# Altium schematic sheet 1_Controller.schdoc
size 431 x 309 mm
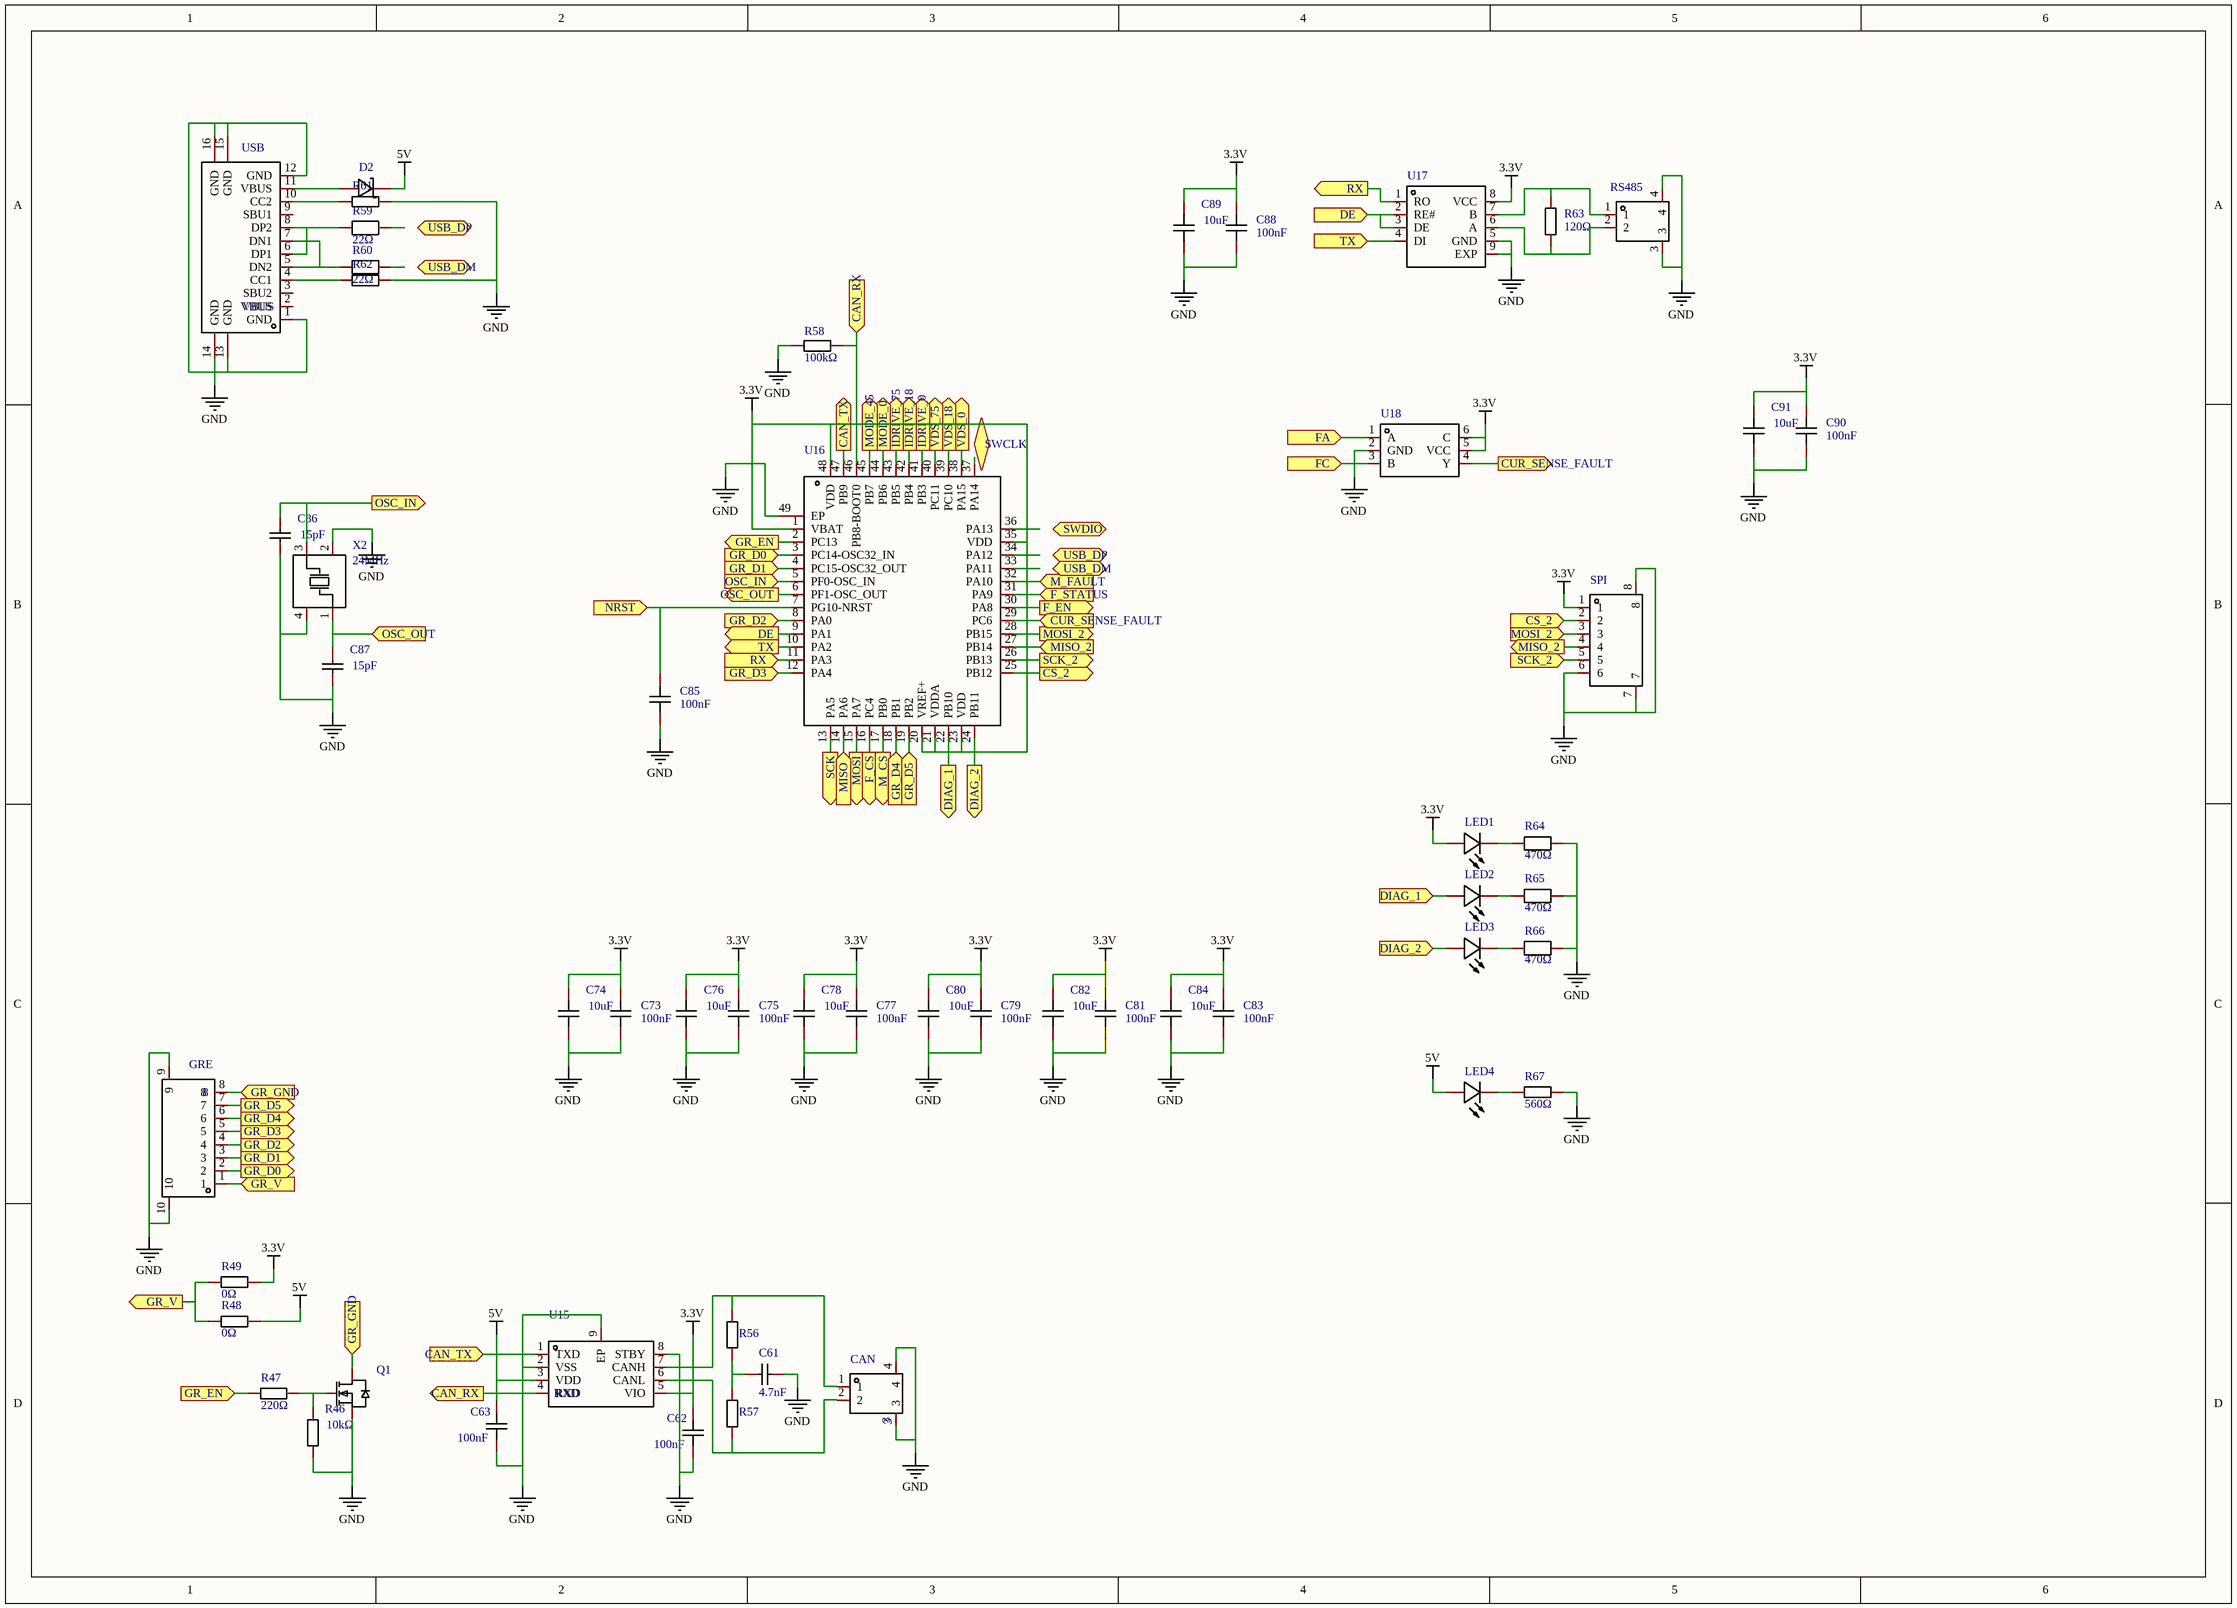
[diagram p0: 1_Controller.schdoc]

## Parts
C61  value 4.7nF  [C0402]  (hidden comment: 0402B472K500CT)
C62  value 100nF  [C0402]  (hidden comment: CC0402KRX7R7BB104)
C63  value 100nF  [C0402]  (hidden comment: CC0402KRX7R7BB104)
C73  value 100nF  [C0402]  (hidden comment: CC0402KRX7R7BB104)
C74  value 10uF  [C0402]  (hidden comment: CL05A106MP5NUNC)
C75  value 100nF  [C0402]  (hidden comment: CC0402KRX7R7BB104)
C76  value 10uF  [C0402]  (hidden comment: CL05A106MP5NUNC)
C77  value 100nF  [C0402]  (hidden comment: CC0402KRX7R7BB104)
C78  value 10uF  [C0402]  (hidden comment: CL05A106MP5NUNC)
C79  value 100nF  [C0402]  (hidden comment: CC0402KRX7R7BB104)
C80  value 10uF  [C0402]  (hidden comment: CL05A106MP5NUNC)
C81  value 100nF  [C0402]  (hidden comment: CC0402KRX7R7BB104)
C82  value 10uF  [C0402]  (hidden comment: CL05A106MP5NUNC)
C83  value 100nF  [C0402]  (hidden comment: CC0402KRX7R7BB104)
C84  value 10uF  [C0402]  (hidden comment: CL05A106MP5NUNC)
C85  value 100nF  [C0402]  (hidden comment: CC0402KRX7R7BB104)
C86  value 15pF  [C0402]  (hidden comment: 0402CG150J500NT)
C87  value 15pF  [C0402]  (hidden comment: 0402CG150J500NT)
C88  value 100nF  [C0402]  (hidden comment: CC0402KRX7R7BB104)
C89  value 10uF  [C0402]  (hidden comment: CL05A106MP5NUNC)
C90  value 100nF  [C0402]  (hidden comment: CC0402KRX7R7BB104)
C91  value 10uF  [C0402]  (hidden comment: CL05A106MP5NUNC)
CAN  NUMBER: 3  [CONN-SMD_A1002WR-S-2P]  (hidden comment: A1002WR-S-2P)
D2  DSK16  [SOD-123_L2.8-W1.8-LS3.7-RD]  (value not drawn)
GRE  NAME: 8  [CONN-SMD_A1002WR-S-8P]  (hidden comment: A1002WR-S-8P)
LED1  MHT136UBCT  [LED0402-RD_BLUE]  (value not drawn)
LED2  MHT136UBCT  [LED0402-RD_BLUE]  (value not drawn)
LED3  MHT136UBCT  [LED0402-RD_BLUE]  (value not drawn)
LED4  MHT136CSCT  [LED0402-RD_ORANGE]  (value not drawn)
Q1  AP2302B  [SOT-23_L2.9-W1.3-P1.90-LS2.4-BR]  (value not drawn)
R46  value 10kΩ  [R0402]  (hidden comment: AC0402FR-0710KL)
R47  value 220Ω  [R0402]  (hidden comment: 0402WGF2200TCE)
R48  value 0Ω  [R0402]  (hidden comment: RC0402FR-070RL)
R49  value 0Ω  [R0402]  (hidden comment: RC0402FR-070RL)
R56  0402WGF604JTCE  [R0402]  (value not drawn)
R57  0402WGF604JTCE  [R0402]  (value not drawn)
R58  value 100kΩ  [R0402]  (hidden comment: PTFR0402B100KN9)
R59  value 22Ω  [R0402]  (hidden comment: AC0402FR-0722RL)
R60  value 22Ω  [R0402]  (hidden comment: AC0402FR-0722RL)
R61  0402WGF5101TCE  [R0402]  (value not drawn)
R62  0402WGF5101TCE  [R0402]  (value not drawn)
R63  value 120Ω  [R0402]  (hidden comment: RC0402FR-07120RL)
R64  value 470Ω  [R0402]  (hidden comment: AC0402FR-07470RL)
R65  value 470Ω  [R0402]  (hidden comment: AC0402FR-07470RL)
R66  value 470Ω  [R0402]  (hidden comment: AC0402FR-07470RL)
R67  value 560Ω  [R0402]  (hidden comment: 0402WGJ0561TCE)
RS485  A1002WR-S-2P  [CONN-SMD_A1002WR-S-2P]  (value not drawn)
SPI  A1002WR-S-6P  [CONN-SMD_A1002WR-S-6P]  (value not drawn)
U15  NAME: RXD  [TDFN-8_L3.0-W2.0-P0.50-TL-EP]  (hidden comment: MCP2542FDT-H/MNY)
U16  STM32G431CBU6  [UFQFPN-48_L7.0-W7.0-P0.50-BL-EP]  (value not drawn)
U17  MAX14841EATA+T  [TDFN-8_L3.0-W3.0-P0.65-BL-EP]  (value not drawn)
U18  SN74LVC1G10DSFR  [X2SON-6_L1.0-W1.0-P0.35-TL]  (value not drawn)
USB  NAME: VBUS  [USB-SMD_GT-USB-7010B]  (hidden comment: GT-USB-7010B)
X2  value 24MHz  [CRYSTAL-SMD_4P-L3.2-W2.5-BL]  (hidden comment: X322524MOB4SI)

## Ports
CAN_RX (in), CAN_RX (out), CAN_TX (in), CAN_TX (out), CS_2 (in), CS_2 (out), CUR_SENSE_FAULT (in), CUR_SENSE_FAULT (out), DE (in), DE (out), DIAG_1 (in), DIAG_1 (out), DIAG_2 (in), DIAG_2 (out), F_CS (out), F_EN (out), F_STATUS (in), FA (in), FC (in), GR_D0 (in), GR_D0 (out), GR_D1 (in), GR_D1 (out), GR_D2 (in), GR_D2 (out), GR_D3 (in), GR_D3 (out), GR_D4 (in), GR_D4 (out), GR_D5 (in), GR_D5 (out), GR_EN (in), GR_EN (out), GR_GND (in), GR_V (in), GR_V (out), IDRIVE_0 (out), IDRIVE_18 (out), IDRIVE_75 (out), M_CS (out), M_FAULT (in), MISO (in), MISO_2 (in), MISO_2 (out), MODE_0 (out), MODE_45 (out), MOSI (out), MOSI_2 (in), MOSI_2 (out), NRST (in), OSC_IN (in), OSC_IN (out), OSC_OUT (in), OSC_OUT (out), RX (in), RX (out), SCK (out), SCK_2 (in), SCK_2 (out), SWCLK (bidir), SWDIO (bidir), TX (in), TX (out), USB_DM (bidir), USB_DP (bidir), VDS_0 (out), VDS_18 (out), VDS_75 (out)

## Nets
3.3V: C62.1 C73.1 C74.2 C75.1 C76.2 C77.1 C78.2 C79.1 C80.2 C81.1 C82.2 C83.1 C84.2 C88.1 C89.2 C90.1 C91.2 LED1.2(A) R49.2 SPI.1 U15.5(VIO) U16.1(VBAT) U16.20(VREF+) U16.21(VDDA) U16.23(VDD) U16.35(VDD) U16.48(VDD) U17.8(VCC) U18.5(VCC) U18.6(C)
5V: C63.1 D2.1(K) LED4.2(A) R48.2 U15.3(VDD)
GND: C61.2 C62.2 C63.2 C73.2 C74.1 C75.2 C76.1 C77.2 C78.1 C79.2 C80.1 C81.2 C82.1 C83.2 C84.1 C85.2 C86.1 C87.1 C88.2 C89.1 C90.2 C91.1 CAN.3 CAN.4 GRE.9 GRE.10 Q1.2(S) R46.1 R58.2 R61.2 R62.2 R64.2 R65.2 R66.2 R67.2 RS485.3 RS485.4 SPI.6 SPI.7 SPI.8 U15.2(VSS) U15.8(STBY) U15.9(EP) U16.49(EP) U17.5(GND) U17.9(EXP) U18.2(GND) USB.1(GND) USB.12(GND) USB.13(GND) USB.14(GND) USB.15(GND) USB.16(GND) X2.2(GND) X2.4(GND)
CAN_RX: R58.1 U15.4(RXD) U16.46(PB8-BOOT0) ; port CAN_RX
CAN_TX: U15.1(TXD) U16.47(PB9) ; port CAN_TX
CS_2: SPI.2 U16.25(PB12) ; port CS_2
CUR_SENSE_FAULT: U16.29(PC6) U18.4(Y) ; port CUR_SENSE_FAULT
DE: U16.9(PA1) U17.2(RE#) U17.3(DE) ; port DE
DIAG_1: LED2.2(A) U16.22(PB10) ; port DIAG_1
DIAG_2: LED3.2(A) U16.24(PB11) ; port DIAG_2
F_CS: U16.16(PC4) ; port F_CS
F_EN: U16.30(PA8) ; port F_EN
F_STATUS: U16.31(PA9) ; port F_STATUS
FA: U18.1(A) ; port FA
FC: U18.3(B) ; port FC
GR_D0: GRE.2 U16.3(PC14-OSC32_IN) ; port GR_D0
GR_D1: GRE.3 U16.4(PC15-OSC32_OUT) ; port GR_D1
GR_D2: GRE.4 U16.8(PA0) ; port GR_D2
GR_D3: GRE.5 U16.12(PA4) ; port GR_D3
GR_D4: GRE.6 U16.18(PB1) ; port GR_D4
GR_D5: GRE.7 U16.19(PB2) ; port GR_D5
GR_EN: R47.1 U16.2(PC13) ; port GR_EN
GR_GND: GRE.8 Q1.3(D) ; port GR_GND
GR_V: GRE.1 R48.1 R49.1 ; port GR_V
IDRIVE_0: U16.41(PB3) ; port IDRIVE_0
IDRIVE_18: U16.42(PB4) ; port IDRIVE_18
IDRIVE_75: U16.43(PB5) ; port IDRIVE_75
M_CS: U16.17(PB0) ; port M_CS
M_FAULT: U16.32(PA10) ; port M_FAULT
MISO: U16.14(PA6) ; port MISO
MISO_2: SPI.4 U16.27(PB14) ; port MISO_2
MODE_0: U16.44(PB6) ; port MODE_0
MODE_45: U16.45(PB7) ; port MODE_45
MOSI: U16.15(PA7) ; port MOSI
MOSI_2: SPI.3 U16.28(PB15) ; port MOSI_2
NRST: C85.1 U16.7(PG10-NRST) ; port NRST
OSC_IN: C86.2 U16.5(PF0-OSC_IN) X2.3(OSC2) ; port OSC_IN
OSC_OUT: C87.2 U16.6(PF1-OSC_OUT) X2.1(OSC1) ; port OSC_OUT
RX: U16.11(PA3) U17.1(RO) ; port RX
SCK: U16.13(PA5) ; port SCK
SCK_2: SPI.5 U16.26(PB13) ; port SCK_2
TX: U16.10(PA2) U17.4(DI) ; port TX
VDS_0: U16.38(PA15) ; port VDS_0
VDS_18: U16.39(PC10) ; port VDS_18
VDS_75: U16.40(PC11) ; port VDS_75
NetC61_1: C61.1 R56.2 R57.1
NetCAN_1: CAN.1 R56.1 U15.7(CANH)
NetCAN_2: CAN.2 R57.2 U15.6(CANL)
NetD2_2: D2.2(A) USB.11(VBUS)
NetLED1_1: LED1.1(K) R64.1
NetLED2_1: LED2.1(K) R65.1
NetLED3_1: LED3.1(K) R66.1
NetLED4_1: LED4.1(K) R67.1
NetQ1_1: Q1.1(G) R46.2 R47.2
NetR59_1: R59.1 USB.6(DP1) USB.8(DP2)
NetR60_1: R60.1 USB.5(DN2) USB.7(DN1)
NetR61_1: R61.1 USB.10(CC2)
NetR62_1: R62.1 USB.4(CC1)
NetR63_1: R63.1 RS485.2 U17.6(A)
NetR63_2: R63.2 RS485.1 U17.7(B)

Not connected (* = marked no-connect by the designer): R59 2; R60 2; U16 33(PA11) 34(PA12) 36(PA13) 37(PA14); USB 2(VBUS) 3(SBU2) 9(SBU1)

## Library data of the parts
C61 = 0402B472K500CT: Capacitance:4.7nF Tolerance:±10% Tolerance:±10% Voltage Rated:50V Temperature Coefficient:X7R; Manufacturer: 华新科(Walsin); Add into BOM: yes; Tolerance: ±10%; Voltage Rated: 50V; Temperature Coefficient: X7R
C62 C63 C73 C75 C77 C79 C81 C83 C85 C88 C90 = CC0402KRX7R7BB104: Capacitance:100nF Tolerance:±10% Tolerance:±10% Voltage Rated:16V Temperature Coefficient:X7R; Manufacturer: YAGEO(国巨); Add into BOM: yes; Tolerance: ±10%; Voltage Rated: 16V; Temperature Coefficient: X7R
C74 C76 C78 C80 C82 C84 C89 C91 = CL05A106MP5NUNC: Capacitance:10uF Tolerance:±20% Tolerance:±20% Voltage Rated:10V Temperature Coefficient:X5R; Manufacturer: SAMSUNG(三星); Symbol: CL05A106MP5NUNC_C315248; Add into BOM: yes; Tolerance: ±20%; Voltage Rated: 10V; Temperature Coefficient: X5R
C86 C87 = 0402CG150J500NT: Capacitance:15pF Tolerance:±5% Tolerance:±5% Voltage Rated:50V Temperature Coefficient:C0G; Manufacturer: FH(风华); Add into BOM: yes; Tolerance: ±5%; Voltage Rated: 50V; Temperature Coefficient: C0G
CAN RS485 = A1002WR-S-2P: Reference Series:SH Pitch:1mm Pins Structure:1x2P Number of Rows:1 Number of PINs Per Row:2 Row Spacing:- Mounting Style:- Contact Material:磷青铜; Manufacturer: CJT(长江连接器); Add into BOM: yes; Reference Series: SH; Pitch: 1mm; Pins Structure: 1x2P; Number of PINs Per Row: 2
D2 = DSK16: Reverse Voltage (Vr):60V Average Rectified Current (Io):1A Forward Voltage (Vf@If):700mV@1A; Manufacturer: MDD; Add into BOM: yes; Reverse Voltage (Vr): 60V; Average Rectified Current (Io): 1A
GRE = A1002WR-S-8P: Reference Series:SH Pitch:1mm Pins Structure:1x8P Number of Rows:1 Number of PINs Per Row:8 Row Spacing:- Mounting Style:- Contact Material:磷青铜; Manufacturer: CJT(长江连接器); Add into BOM: yes; Reference Series: SH; Pitch: 1mm; Pins Structure: 1x8P
LED1-LED3 = MHT136UBCT: Emitted Color:蓝灯 Diode Configuration:- Lens Color:无色透明 Dominant Wavelength:460nm~475nm Dominant Wavelength:460nm~475nm Peak Wavelength:468nm Color Temperature:- Color Temperature:- Luminous Flux (@25):- Forward Current:5mA Forward Voltage (VF):3V Luminou; Manufacturer: MEIHUA(美华科技); Add into BOM: yes; Emitted Color: 蓝灯; Lens Color: 无色透明; Peak Wavelength: 468nm; Forward Current: 5mA; Forward Voltage (VF): 3V; Luminous Intensity: 72mcd; Power Dissipation: 95mW; Viewing Angle: 120°
LED4 = MHT136CSCT: Emitted Color:橙灯 Diode Configuration:- Lens Color:无色透明 Dominant Wavelength:600.5nm~612.5nm Dominant Wavelength:600.5nm~612.5nm Peak Wavelength:611nm Color Temperature:- Color Temperature:- Luminous Flux (@25):- Forward Current:5mA Forward Voltage (VF):2.; Manufacturer: MEIHUA(美华科技); Add into BOM: yes; Emitted Color: 橙灯; Lens Color: 无色透明; Peak Wavelength: 611nm; Forward Current: 5mA; Forward Voltage (VF): 2.2V; Luminous Intensity: 72mcd; Power Dissipation: 60mW; Viewing Angle: 120°
Q1 = AP2302B: Type:N沟道 Drain Source Voltage (Vdss):20V Continuous Drain Current (Id):2.8A Power Dissipation (Pd):350mW Drain Source On Resistance (RDS(on)@Vgs,Id):55mΩ@4.5V,2.8A Gate Threshold Voltage (Vgs(th)@Id):1.2V@50A; Manufacturer: ALLPOWER(铨力); Add into BOM: yes; Type: N沟道; Drain Source Voltage (Vdss): 20V; Power Dissipation (Pd): 350mW
R46 = AC0402FR-0710KL: Type:厚膜电阻 Resistance:10kΩ Tolerance:±1% Tolerance:±1% Power(Watts):62.5mW Temperature Coefficient:±100ppm/ Temperature Coefficient:±100ppm/ Overload Voltage (Max):50V Operating Temperature Range:-55~+155 Operating Temperature Range:-55~+155; Manufacturer: YAGEO(国巨); Add into BOM: yes; Tolerance: ±1%; Power(Watts): 62.5mW; Overload Voltage (Max): 50V
R47 = 0402WGF2200TCE: Type:厚膜电阻 Resistance:220Ω Tolerance:±1% Power(Watts):1/16W Temperature Coefficient:±100ppm/ Temperature Coefficient:±100ppm/ Overload Voltage (Max):50V Operating Temperature Range:-55~+155 Operating Temperature Range:-55~+155; Manufacturer: UNI-ROYAL(厚声); Add into BOM: yes; Tolerance: ±1%; Power(Watts): 1/16W; Overload Voltage (Max): 50V
R48 = RC0402FR-070RL: Temperature Coefficient:- Temperature Coefficient:- Power(Watts):1/16W Tolerance:±1% Resistance:0Ω Overload Voltage (Max):50V Operating Temperature Range:-55~+155 Operating Temperature Range:-55~+155; Manufacturer: YAGEO(国巨); Add into BOM: no; Convert to PCB: yes; Power(Watts): 1/16W; Tolerance: ±1%; Overload Voltage (Max): 50V
R49 = RC0402FR-070RL: Temperature Coefficient:- Temperature Coefficient:- Power(Watts):1/16W Tolerance:±1% Resistance:0Ω Overload Voltage (Max):50V Operating Temperature Range:-55~+155 Operating Temperature Range:-55~+155; Manufacturer: YAGEO(国巨); Add into BOM: yes; Power(Watts): 1/16W; Tolerance: ±1%; Overload Voltage (Max): 50V
R56 R57 = 0402WGF604JTCE: Manufacturer: UNI-ROYAL(厚声); Add into BOM: yes
R58 = PTFR0402B100KN9: Type:薄膜电阻 Resistance:100kΩ Tolerance:±0.1% Power(Watts):60mW Temperature Coefficient:±10ppm/ Temperature Coefficient:±10ppm/ Overload Voltage (Max):75V Operating Temperature Range:-55~+125 Operating Temperature Range:-55~+125; Manufacturer: RESI(开步睿思）; Add into BOM: yes; Tolerance: ±0.1%; Power(Watts): 60mW; Temperature Coefficient: ±10ppm/; Overload Voltage (Max): 75V
R59 R60 = AC0402FR-0722RL: Body Length:- Tolerance:±1% Operating Temperature Range:-55~+155 Operating Temperature Range:-55~+155 φD:- Body Height:- Body Width:- Overload Voltage (Max):50V Type:厚膜电阻 Power(Watts):62.5mW Temperature Coefficient:±100ppm/ Temperature Coefficient:±1; Manufacturer: YAGEO(国巨); Add into BOM: yes; Tolerance: ±1%; Overload Voltage (Max): 50V; Power(Watts): 62.5mW
R61 R62 = 0402WGF5101TCE: Manufacturer: UNI-ROYAL(厚声); Add into BOM: yes
R63 = RC0402FR-07120RL: Type:厚膜电阻 Resistance:120Ω Tolerance:±1% Tolerance:±1% Power(Watts):62.5mW Temperature Coefficient:±100ppm/ Temperature Coefficient:±100ppm/ Overload Voltage (Max):50V Operating Temperature Range:-55~+155 Operating Temperature Range:-55~+155; Manufacturer: YAGEO(国巨); Add into BOM: yes; Tolerance: ±1%; Power(Watts): 62.5mW; Overload Voltage (Max): 50V
R64-R66 = AC0402FR-07470RL: Type:厚膜电阻 Resistance:470Ω Tolerance:±1% Tolerance:±1% Power(Watts):62.5mW Temperature Coefficient:±100ppm/ Temperature Coefficient:±100ppm/ Overload Voltage (Max):50V Operating Temperature Range:-55~+155 Operating Temperature Range:-55~+155; Manufacturer: YAGEO(国巨); Add into BOM: yes; Tolerance: ±1%; Power(Watts): 62.5mW; Overload Voltage (Max): 50V
R67 = 0402WGJ0561TCE: Type:厚膜电阻 Resistance:560Ω Tolerance:±5% Power(Watts):1/16W Temperature Coefficient:±100ppm/ Temperature Coefficient:±100ppm/ Overload Voltage (Max):50V Operating Temperature Range:-55~+155 Operating Temperature Range:-55~+155; Manufacturer: UNI-ROYAL(厚声); Add into BOM: yes; Tolerance: ±5%; Power(Watts): 1/16W; Overload Voltage (Max): 50V
SPI = A1002WR-S-6P: Reference Series:SH Pitch:1mm Pins Structure:1x6P Number of Rows:1 Number of PINs Per Row:6 Row Spacing:- Mounting Style:- Contact Material:磷青铜; Manufacturer: CJT(长江连接器); Add into BOM: yes; Reference Series: SH; Pitch: 1mm; Pins Structure: 1x6P; Number of PINs Per Row: 6
U15 = MCP2542FDT-H/MNY: Manufacturer: MICROCHIP(美国微芯); Manufacturer Part: MCP2542WFDT-H/MNY; Add into BOM: yes
U16 = STM32G431CBU6: Core Size:- Program Memory Type:- Core Processor:- Speed:- Voltage - Supply (Vcc/Vdd):- Program Memory Size:- RAM Size:- EEPROM Size:- Number of I/O:- A/D:- D/A:- PWM:- LCD:- UART/USART:- SPI:- I2C（SMBUS/PMBUS）:- USB Device:- USB Host/OTG:- CAN:- Ethernet; Manufacturer: ST(意法半导体); Add into BOM: yes
U17 = MAX14841EATA+T: Types:收发器 Driver/receiver:1/1 Data Rate:40Mbps Data Rate:40Mbps Supply Voltage:3V~3.6V Supply Voltage:3V~3.6V; Manufacturer: MAXIM(美信); Add into BOM: yes; Types: 收发器; Driver/receiver: 1/1; Data Rate: 40Mbps
U18 = SN74LVC1G10DSFR: Series:74LVC Logic Type:与非门 Number of Circuits/Elements:1 Number of Inputs/Bits per Element:3 Supply Voltage（Single）:1.65V ~ 5.5V Quiescent Current (Max):10A Current - Output High, Low:32mA、32mA Operating Temperature:-40~125 Max Propagation Delay @ V,; Manufacturer: TI(德州仪器); Add into BOM: yes; Logic Type: 与非门; Number of Circuits/Elements: 1; Number of Inputs/Bits per Element: 3; Quiescent Current (Max): 10A; Max Propagation Delay @ V, Max CL: 3.6ns @ 5V，50pF
USB = GT-USB-7010B: Connector Type:Type-C Standard:- Gender:母座 Number of Contacts:16 Number of Ports:1 Mounting Style:卧贴 Current Rating - Power (Max):5A Operating Temperature Range:-30~+85 Operating Temperature Range:-30~+85; Manufacturer: G-Switch(品赞); Add into BOM: yes; Connector Type: Type-C; Gender: 母座; Number of Contacts: 16; Number of Ports: 1; Current Rating - Power (Max): 5A
X2 = X322524MOB4SI: Crystal Type:贴片无源晶振 Frequency:24MHz Frequency Tolerance:±10ppm Frequency Tolerance:±10ppm Frequency Stability:±30ppm Frequency Stability:±30ppm Load Capacitance:12pF Operating Temperature:-40~+85 Operating Temperature:-40~+85; Manufacturer: YXC扬兴科技; Add into BOM: yes; Crystal Type: 贴片无源晶振; Frequency Tolerance: ±10ppm; Frequency Stability: ±30ppm; Load Capacitance: 12pF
